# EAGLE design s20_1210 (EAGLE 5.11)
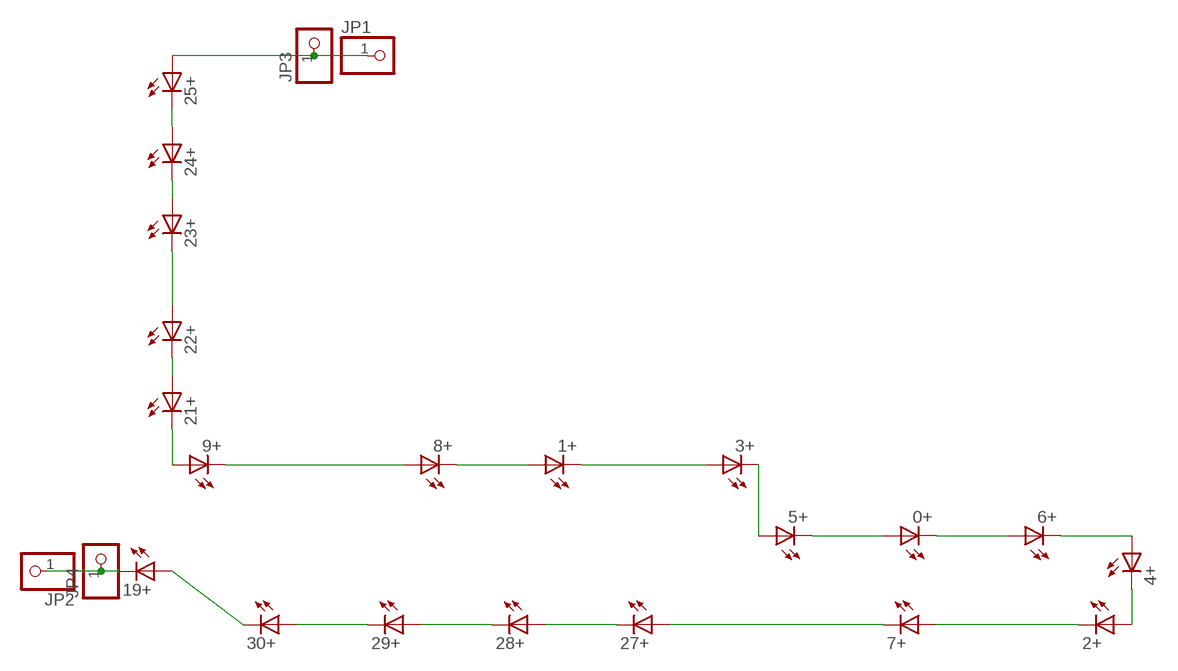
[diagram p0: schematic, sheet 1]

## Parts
0+  LED1210  [1210]
1+  LED1210  [1210]
2+  LED1210  [1210]
3+  LED1210  [1210]
4+  LED1210  [1210]
5+  LED1210  [1210]
6+  LED1210  [1210]
7+  LED1210  [1210]
8+  LED1210  [1210]
9+  LED1210  [1210]
19+  LED1210  [1210]
21+  LED1210  [1210]
22+  LED1210  [1210]
23+  LED1210  [1210]
24+  LED1210  [1210]
25+  LED1210  [1210]
27+  LED1210  [1210]
28+  LED1210  [1210]
29+  LED1210  [1210]
30+  LED1210  [1210]
JP1  PINHD-1X11MM6  [1X1MM8]
JP2  PINHD-1X11MM6  [1X1MM8]
JP3  PINHD-1X11X0.4  [1X01]
JP4  PINHD-1X11X0.4  [1X01]

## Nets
MINUS: 19+.P$2(C) JP2.1 JP4.1
N$4: 19+.P$1(A) 30+.P$2(C)
N$6: 8+.P$1(A) 9+.P$2(C)
N$7: 29+.P$2(C) 30+.P$1(A)
N$8: 28+.P$2(C) 29+.P$1(A)
N$9: 27+.P$2(C) 28+.P$1(A)
N$12: 2+.P$2(C) 7+.P$1(A)
N$13: 7+.P$2(C) 27+.P$1(A)
N$14: 2+.P$1(A) 4+.P$2(C)
N$15: 4+.P$1(A) 6+.P$2(C)
N$16: 0+.P$2(C) 6+.P$1(A)
N$17: 0+.P$1(A) 5+.P$2(C)
N$18: 3+.P$2(C) 5+.P$1(A)
N$19: 1+.P$2(C) 3+.P$1(A)
N$20: 1+.P$1(A) 8+.P$2(C)
N$23: 9+.P$1(A) 21+.P$2(C)
N$24: 21+.P$1(A) 22+.P$2(C)
N$25: 22+.P$1(A) 23+.P$2(C)
N$26: 24+.P$1(A) 25+.P$2(C)
N$28: 23+.P$1(A) 24+.P$2(C)
PLUS: 25+.P$1(A) JP1.1 JP3.1

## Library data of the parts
0+ 1+ 2+ 3+ 4+ 5+ 6+ 7+ 8+ 9+ 19+ 21+ 22+ 23+ 24+ 25+ 27+ 28+ 29+ 30+ = led(2):LED: LED
JP1-JP4 = pinhead:PINHD-1X1: PIN HEADER

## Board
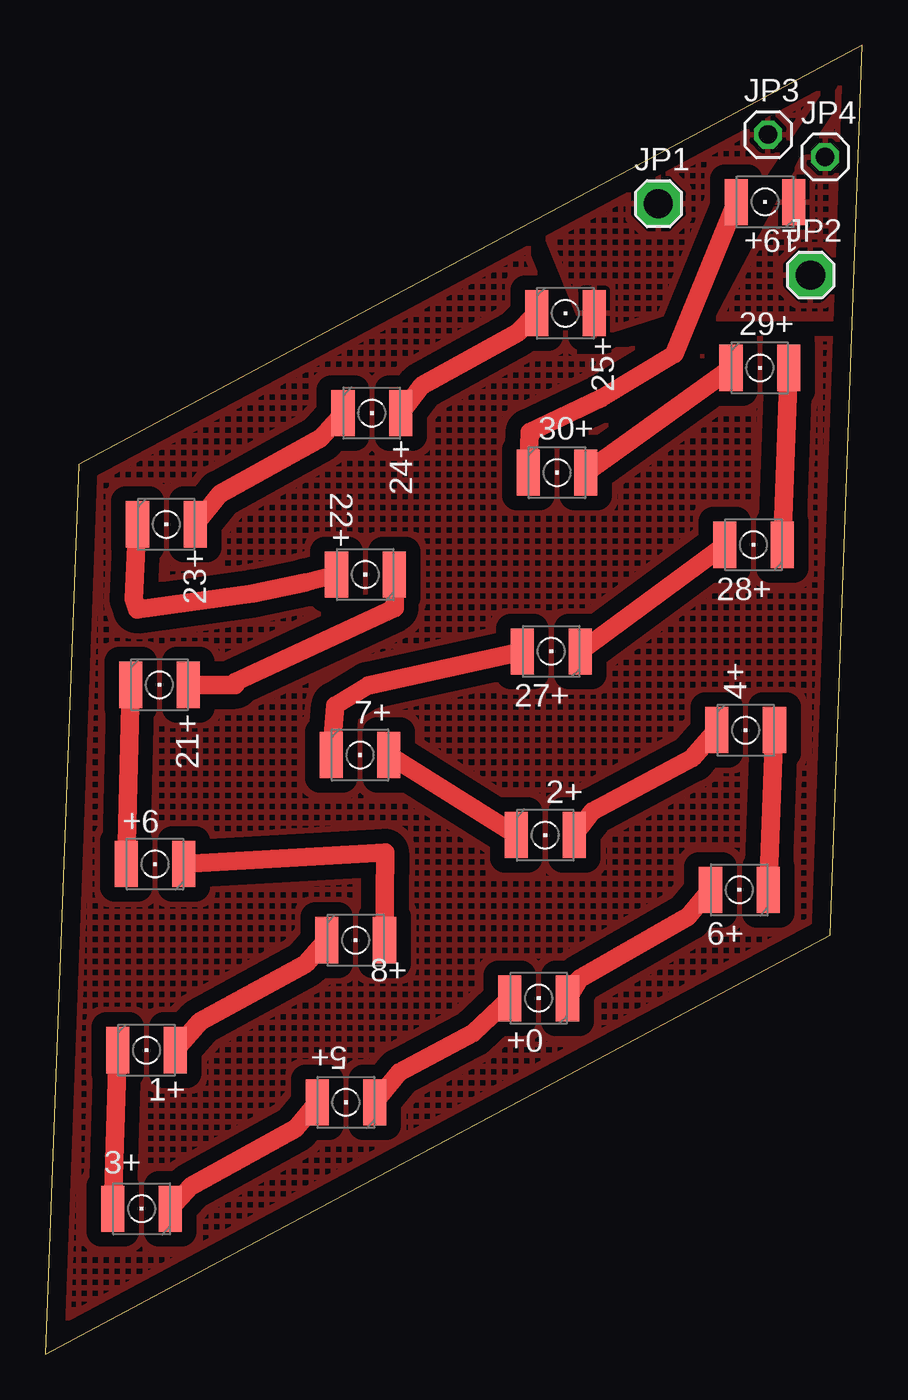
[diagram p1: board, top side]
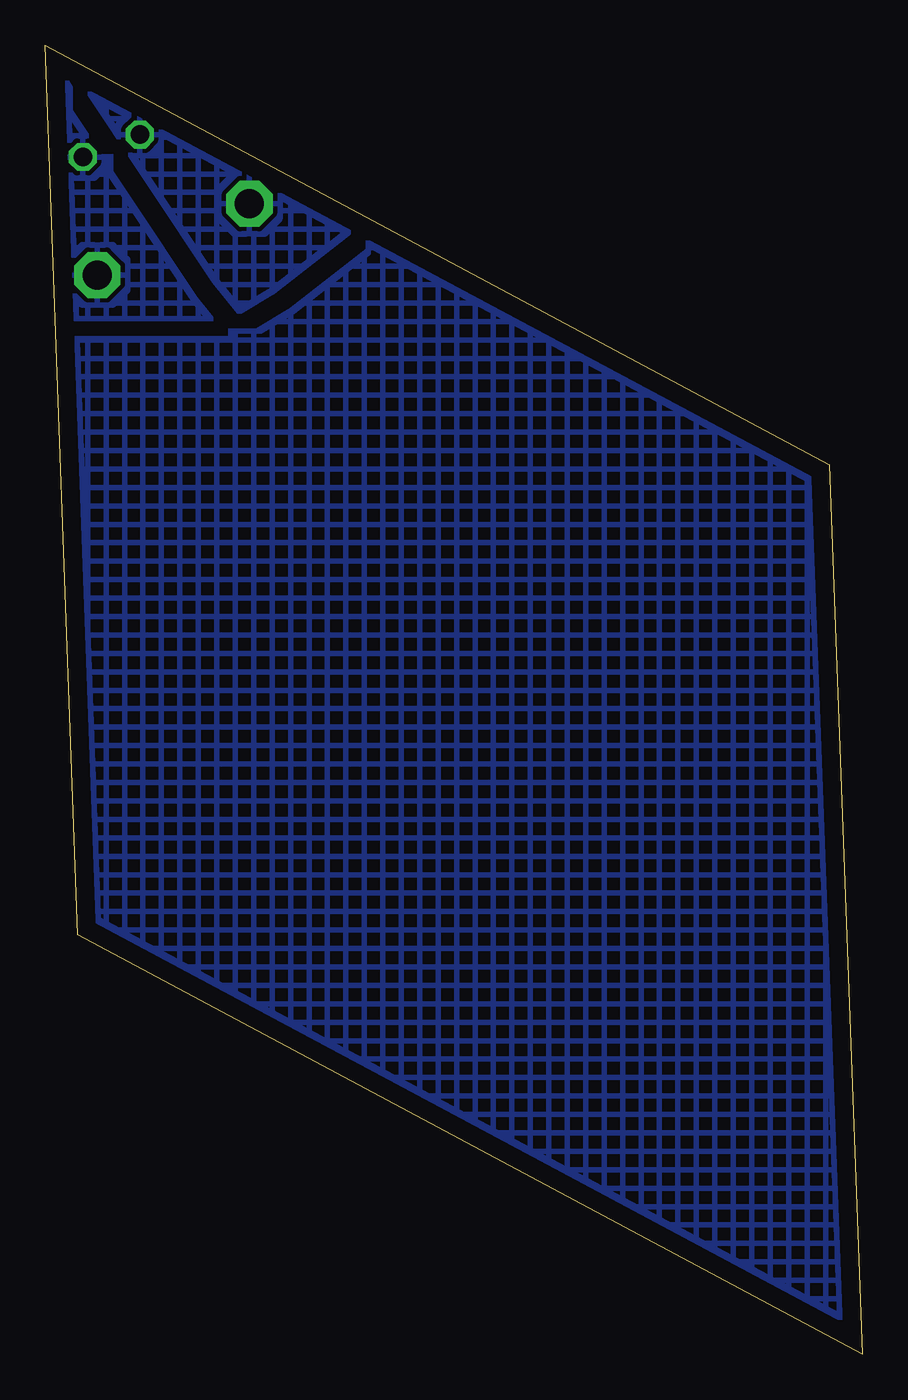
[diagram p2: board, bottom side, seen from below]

Size 45 x 72.11 mm. Coordinates in mm from the lower left corner, seen from the top.
Outline: 0,0 43.22,23.09 45,72.11 1.83,49.01 0,0
Copper layers (1*16): Top 0.035mm / dielectric 1.5mm / Bottom 0.035mm
Design rules "default": minimum track width 10mil, minimum drill 24mil, track to track 8mil, track to pad 8mil, pad to pad 8mil, via to via 8mil, smd to smd 8mil, copper to edge 40mil, drill to drill 8mil, minimum pad ring 10mil, minimum via ring 8mil, stop-mask expansion 4mil, vias tented up to drill 0mil, thermal gap 10mil

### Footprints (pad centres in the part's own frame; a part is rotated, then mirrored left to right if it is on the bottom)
1210 = smd 1.27 x 2.54: P$1 1.587,0; P$2 -1.587,0
1X1MM8 = drill 1.6 pad 2.54 octagon: 1 0,0
1X01 = drill 1.016 octagon: 1 0,0

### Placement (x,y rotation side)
0+  27.17,19.61 180 top
1+  5.57,16.75 0 top
2+  27.53,28.6 0 top
3+  5.3,8.01 180 top
4+  38.57,34.38 0 top
5+  16.55,13.87 180 top
6+  38.22,25.58 180 top
7+  17.33,33.01 0 top
8+  17.09,22.81 0 top
9+  6.04,27 180 top
19+  39.64,63.48 180 top
21+  6.28,36.88 0 top
22+  17.62,42.95 180 top
23+  6.66,45.72 0 top
24+  17.98,51.85 0 top
25+  28.64,57.35 0 top
27+  27.86,38.72 180 top
28+  39,44.59 180 top
29+  39.35,54.34 0 top
30+  28.18,48.57 0 top
JP1  33.76,63.39 0 top
JP2  42.14,59.46 0 top
JP3  39.8,67.19 0 top
JP4  42.94,65.96 0 top

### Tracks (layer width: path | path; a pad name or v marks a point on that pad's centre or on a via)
MINUS
  pour Top (isolate 0.813, rank 2, hatched): 44.45,71.12 37.01,57.05 43.36,57.05
  pour Bottom (isolate 0.813, rank 2, hatched): 44.45,71.12 35.74,57.05 43.36,57.05
N$1
  pour Top (isolate 0.813, rank 3, hatched): 2.54,49.53 0,0 43.18,24.13 44.45,71.12
  pour Bottom (isolate 0.813, rank 3, hatched): 2.54,49.53 0,0 43.18,24.13 44.45,71.12
N$4
  Top 1.016: 30+.P$2 26.67,50.8 30.62,52.68 34.65,55.11 19+.P$1
N$6
  Top 1.016: 8+.P$1 18.71,27.63 9+.P$2
N$7
  Top 1.016: 30+.P$1 29+.P$2
N$8
  Top 1.016: 28+.P$2 29+.P$1
N$9
  Top 1.016: 27+.P$2 28+.P$1
N$12
  Top 1.016: 7+.P$1 2+.P$2
N$13
  Top 1.016: 7+.P$2 15.97,35.74 17.78,36.83 27+.P$1
N$14
  Top 1.016: 2+.P$1 30.13,29.91 35.63,32.84 4+.P$2
N$15
  Top 1.016: 6+.P$2 4+.P$1
N$16
  Top 1.016: 0+.P$2 29.41,20.67 35.41,24.11 6+.P$1
N$17
  Top 1.016: 5+.P$2 19.5,15.53 23.56,17.69 0+.P$1
N$18
  Top 1.016: 3+.P$2 8.01,9.24 13.8,12.45 5+.P$1
N$19
  Top 1.016: 3+.P$1 1+.P$2
N$20
  Top 1.016: 1+.P$1 8.53,18.33 14.33,21.51 8+.P$2
N$23
  Top 1.016: 9+.P$1 21+.P$2
N$24
  Top 1.016: 21+.P$1 10.45,36.88 10.45,37.02 19.23,41.12 19.23,42.95 22+.P$2
N$25
  Top 1.016: 22+.P$1 14.32,42.52 11.43,41.91 5.05,41.03 4.86,41.61 23+.P$2
N$26
  Top 1.016: 24+.P$1 20.73,53.36 26.03,56.29 25+.P$2
N$28
  Top 1.016: 23+.P$1 9.61,47.4 15.16,50.46 24+.P$2
PLUS
  pour Top (isolate 0.813, hatched): 42.98,70.04 35.71,59.13 34.31,57.4 29.91,56 27.21,62.61
  pour Bottom (isolate 0.813, hatched): 42.98,70.04 35.71,59.13 34.31,57.4 32.45,58.54 27.21,62.61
